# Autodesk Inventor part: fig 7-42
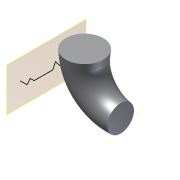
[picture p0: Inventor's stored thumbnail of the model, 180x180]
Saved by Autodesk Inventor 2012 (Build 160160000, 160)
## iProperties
Created: 2011-07
Part Number: fig 7-42
Material: Default
Document SubType Name: Modeling
Designer: CadCim
Density: 1 g/cm^3
Author: CadCim
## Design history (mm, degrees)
sketch "Sketch1"
  geometry: 1 further point
sketch "Sketch2"
  geometry: L1 (9, 5.1)-(9, 4.1); L2 (2.9, -2)-(2.9, -2); A1 r 6.1 centre (2.9, 4.1) between (2.9, -2) and (9, 4.1); 1 further point
  constraints: 4 end point, 2 point on circle, 2 tangent, 1 centre point, 1 perpendicular, 1 vertical
workplane "Work Plane1"
sketch "Sketch3"
  geometry: C1 r 2.236 at (0, 0); 1 further point
  constraints: 1 centre point
sweep "Sweep1" sketch "Sketch3" dims "d0" = 5 deg
workplane "Work Plane3"
sketch "Sketch5"
  geometry: L1 (5, -1)-(4, -1); L2 (4, -1)-(3, 0); L3 (3, 0)-(2.774, -1); L4 (2.774, -1)-(2, 0); L5 (2, 0)-(1.572, -1); L6 (1.572, -1)-(0.798, 0); L7 (0.798, 0)-(0.37, -1); L8 (0.37, -1)-(-2.804, -1); L9 (-2.804, -1)-(-3.466, -0.337); L10 (-3.466, -0.337)-(-4, -1); L11 (-4, -1)-(-5.153, 0.153); 1 further point
  constraints: 22 end point, 4 parallel, 1 collinear, 1 horizontal
body "Solid1"
other parameters: "d1" = -14.75
